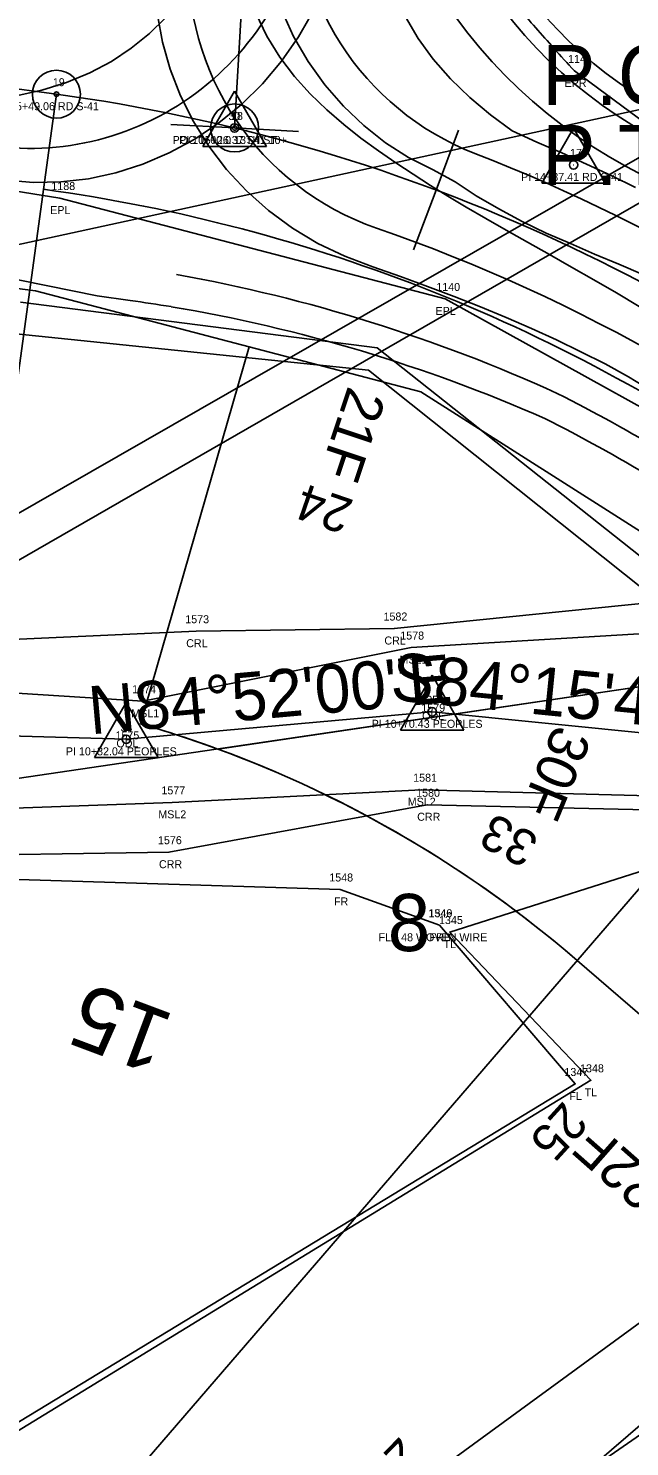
# Model space of a CAD drawing. Extents: x 1812113 to 1819860, y 1177290 to 1181185.
# Drawn here: x 1813637.8 to 1813713, y 1178588.3 to 1178765.6 of the extents above; entities that cross this region are included whole.
import ezdxf

# ---------------------------------------------------------------- set-up
doc = ezdxf.new("R2010")
doc.units = 0
for name, color, linetype in [('RD_EX_DV_Prop', 7, 'Continuous'), ('RD_EX_DV_TX_Prop', 7, 'Continuous'), ('RD_EX_Fence_Other', 7, 'Continuous'), ('RD_EX_Fence_Other_txCode', 7, 'Continuous'), ('RD_EX_H2O', 7, 'Continuous'), ('RD_EX_H2O_txCode', 7, 'Continuous'), ('RD_EX_Misc', 7, 'Continuous'), ('RD_EX_Misc_txCode', 7, 'Continuous'), ('RD_EX_Road', 7, 'Continuous'), ('RD_EX_Road_txCode', 7, 'Continuous'), ('RD_EX_RW', 7, 'Continuous'), ('RD_EX_UT', 7, 'Continuous'), ('RD_EX_VEG', 7, 'Continuous'), ('RD_EX_VEG_txCode', 7, 'Continuous'), ('RD_HC_CL', 7, 'Continuous'), ('RD_HC_Data', 7, 'Continuous'), ('RD_HC_Data_Tic', 7, 'Continuous'), ('RD_HC_TX_Sta50', 7, 'Continuous'), ('RD_HC_TX_StaOther', 7, 'Continuous'), ('RD_HC_txCode', 7, 'Continuous'), ('RD_PD_ALT1_TnTmp', 7, 'Continuous'), ('RD_PD_ALT1_TrvlWay', 7, 'Continuous'), ('RD_PD_CstnLmt', 7, 'Continuous'), ('RD_PD_DR_ErosCtrl', 7, 'Continuous'), ('RD_PD_GR', 7, 'Continuous'), ('RD_PD_PatLn1', 7, 'Continuous'), ('RD_PD_PatLn2', 7, 'Continuous'), ('RD_PD_RW', 7, 'Continuous'), ('RD_Sketch5', 7, 'Continuous'), ('RD_Sketch7', 7, 'Continuous'), ('RD_Sketch8', 7, 'Continuous'), ('RD_SMD_Locator', 7, 'Continuous'), ('ROW_Obtain_T3', 7, 'Continuous')]:
    doc.layers.add(name, color=color, linetype=linetype)

msp = doc.modelspace()

# ---------------------------------------------------------------- linework, layer by layer
at = {"layer": 'RD_EX_DV_Prop'}
msp.add_line((1813739.05, 1178686.93), (1813534.09, 1178656.72), dxfattribs=at)
at = {"layer": 'RD_EX_Fence_Other'}
for points in [[(1813495.44, 1178671.73), (1813524.97, 1178674.61), (1813567.3, 1178667.34), (1813625.77, 1178659.53), (1813676.75, 1178657.94), (1813689.16, 1178653.47)], [(1813689.16, 1178653.47), (1813706.15, 1178633.63), (1813541.42, 1178533.61)]]:
    msp.add_lwpolyline(points, dxfattribs=at)
at = {"layer": 'RD_EX_H2O'}
for points in [[(1813499.62, 1178706.37), (1813533.11, 1178716.31), (1813566.87, 1178706.45), (1813581.02, 1178703.79), (1813602.73, 1178697.66), (1813630.18, 1178688.94), (1813658.74, 1178690.22), (1813683.52, 1178690.56), (1813733.77, 1178695.63), (1813767.86, 1178725.16), (1813778.94, 1178729.95)], [(1813494.93, 1178677.14), (1813538.08, 1178685.02), (1813548.67, 1178684.4), (1813554.06, 1178674.83), (1813572.78, 1178667.8), (1813599.8, 1178663.18), (1813623.26, 1178662.12), (1813655.35, 1178662.6), (1813687.65, 1178668.53), (1813720.68, 1178667.78), (1813740.16, 1178669.89), (1813749.02, 1178672.08), (1813765.42, 1178660.89)]]:
    msp.add_lwpolyline(points, dxfattribs=at)
at = {"layer": 'RD_EX_Misc'}
for points in [[(1813405.71, 1178572.74), (1813779.17, 1178786.7), (1813799.35, 1179222.21)], [(1813408.47, 1178567.92), (1813786.33, 1178785.29), (1813804.76, 1179221.83)], [(1813573.26, 1178698.61), (1813581.18, 1178685.42), (1813588.27, 1178683.03), (1813621.87, 1178683.41), (1813652.09, 1178681.47), (1813685.62, 1178688.18), (1813723.85, 1178690.46), (1813735.91, 1178692.91), (1813768.22, 1178723.13), (1813784.54, 1178734.4), (1813800.79, 1178738.46), (1813839.24, 1178736.87), (1813863.9, 1178734.39), (1813884.49, 1178732.56), (1813903.28, 1178733.23)], [(1813591.15, 1178668.77), (1813628.98, 1178667.84), (1813655.76, 1178668.83), (1813686.95, 1178670.41), (1813726.51, 1178669.36), (1813738.94, 1178670.71), (1813788.68, 1178718.19), (1813806.25, 1178725.66), (1813819.18, 1178726.19), (1813847.08, 1178721.31), (1813860.38, 1178717.65), (1813871.97, 1178724.25), (1813883.92, 1178723.48), (1813902.67, 1178722.42)]]:
    msp.add_lwpolyline(points, dxfattribs=at)
at = {"layer": 'RD_EX_Road'}
msp.add_line((1813739.94, 1178735.23), (1813706.04, 1178760.25), dxfattribs=at)
msp.add_lwpolyline([(1813732.94, 1178707.95), (1813689.88, 1178731.75), (1813641.71, 1178744.36), (1813593.37, 1178752.09), (1813544.49, 1178758.77), (1813495.45, 1178766.29), (1813446.8, 1178774.66), (1813426.54, 1178777.95), (1813403.21, 1178782.55), (1813398.65, 1178783.84), (1813350.68, 1178796.09), (1813343.23, 1178797.92), (1813318.7, 1178804.23), (1813303.26, 1178808.85), (1813256.8, 1178823.17), (1813209.81, 1178838.91), (1813163.27, 1178855.57)], dxfattribs=at)
msp.add_open_spline([(1813706.04, 1178760.25), (1813693.68, 1178773.78), (1813687.15, 1178785.68), (1813683.91, 1178796.53)], degree=2, dxfattribs=at)
at = {"layer": 'RD_EX_RW'}
for p, q in [((1813539.17, 1178745.92), (1813638.67, 1178732.75)), ((1813638.67, 1178732.75), (1813686.84, 1178720.14)), ((1813686.84, 1178720.14), (1813739.05, 1178686.93)), ((1813724.98, 1178611.66), (1813565.45, 1178495.22))]:
    msp.add_line(p, q, dxfattribs=at)
at = {"layer": 'RD_EX_UT'}
msp.add_lwpolyline([(1813817.45, 1178777.9), (1813490.2, 1178706.76), (1813294.33, 1178669.42)], dxfattribs=at)
at = {"layer": 'RD_EX_VEG'}
msp.add_lwpolyline([(1813569.58, 1178500.76), (1813635.35, 1178535.15), (1813737.8, 1178606.06), (1813775.9, 1178641.25), (1813752.75, 1178672.45), (1813690.46, 1178652.62), (1813708.11, 1178634.09), (1813540.71, 1178531.72)], dxfattribs=at)
at = {"layer": 'RD_HC_CL'}
for p, q in [((1813663.56, 1178753.12), (1813680.53, 1179052.64)), ((1813641.28, 1178757.34), (1813538.22, 1178771.42)), ((1813650.02, 1178676.71), (1813688.26, 1178680.15)), ((1813688.26, 1178680.15), (1813722.87, 1178676.67)), ((1813618, 1178677.68), (1813650.02, 1178676.71))]:
    msp.add_line(p, q, dxfattribs=at)
msp.add_arc((1813611.44, 1178539), 220.37, 49.2184, 82.2191, dxfattribs=at)
at = {"layer": 'RD_HC_Data'}
for p, q in [((1813641.28, 1178757.34), (1813620.6, 1178606.01)), ((1813659.59, 1178750.82), (1813663.56, 1178757.7)), ((1813663.56, 1178757.7), (1813667.53, 1178750.82)), ((1813701.98, 1178746.21), (1813705.95, 1178753.09)), ((1813705.95, 1178753.09), (1813709.92, 1178746.21)), ((1813659.59, 1178750.82), (1813667.53, 1178750.82)), ((1813701.98, 1178746.21), (1813709.92, 1178746.21)), ((1813755.38, 1178705.86), (1813645.02, 1178577.93)), ((1813684.29, 1178677.85), (1813688.26, 1178684.73)), ((1813688.26, 1178684.73), (1813692.23, 1178677.85)), ((1813646.05, 1178674.42), (1813650.02, 1178681.3)), ((1813650.02, 1178681.3), (1813653.99, 1178674.42)), ((1813684.29, 1178677.85), (1813692.23, 1178677.85)), ((1813646.05, 1178674.42), (1813653.99, 1178674.42))]:
    msp.add_line(p, q, dxfattribs=at)
for centre, radius in [((1813641.28, 1178757.34), 3), ((1813641.28, 1178757.34), 0.282), ((1813663.56, 1178753.12), 3), ((1813663.56, 1178753.12), 0.529), ((1813663.56, 1178753.12), 0.282), ((1813705.95, 1178748.5), 0.529), ((1813688.26, 1178680.15), 0.529), ((1813650.02, 1178676.71), 0.529)]:
    msp.add_circle(centre, radius, dxfattribs=at)
at = {"layer": 'RD_HC_Data_Tic'}
for p, q in [((1813663.56, 1178753.12), (1813655.57, 1178753.57)), ((1813663.56, 1178753.12), (1813671.54, 1178752.66)), ((1813688.75, 1178745.36), (1813691.55, 1178752.85)), ((1813688.75, 1178745.36), (1813685.94, 1178737.87))]:
    msp.add_line(p, q, dxfattribs=at)
at = {"layer": 'RD_PD_ALT1_TrvlWay'}
for centre, radius, start, end in [((1813743.64, 1178805.37), 65, 176.7565, 243.6045), ((1813611.44, 1178539), 208.37, 54.383, 82.2191)]:
    msp.add_arc(centre, radius, start, end, dxfattribs=at)
at = {"layer": 'RD_PD_CstnLmt'}
for p, q in [((1813636.78, 1178731.34), (1813681.37, 1178725.65)), ((1813681.37, 1178725.65), (1813714.27, 1178699.59))]:
    msp.add_line(p, q, dxfattribs=at)
msp.add_arc((1813611.44, 1178539), 255.97, 56.8168, 69.1681, dxfattribs=at)
at = {"layer": 'RD_PD_DR_ErosCtrl'}
for p, q in [((1813680.31, 1178722.84), (1813636.23, 1178727.38)), ((1813714.98, 1178695.21), (1813680.31, 1178722.84)), ((1813732.88, 1178606.97), (1813693.96, 1178573.58))]:
    msp.add_line(p, q, dxfattribs=at)
msp.add_arc((1813611.44, 1178539), 258.97, 56.8421, 70.5446, dxfattribs=at)
at = {"layer": 'RD_PD_GR'}
for centre, radius, start, end in [((1813743.64, 1178803.52), 58.53, 176.7565, 245.2829), ((1813620.41, 1178536.16), 201.87, 65.5658, 79.7574), ((1813613.06, 1178539.68), 201.87, 54.383, 63.2527)]:
    msp.add_arc(centre, radius, start, end, dxfattribs=at)
at = {"layer": 'RD_PD_PatLn1'}
for p, q in [((1813646.37, 1178732.12), (1813583.13, 1178745.1)), ((1813650.52, 1178731.55), (1813646.37, 1178732.12))]:
    msp.add_line(p, q, dxfattribs=at)
for centre, radius, start, end in [((1813743.64, 1178803.52), 55.03, 176.7565, 245.4118), ((1813623.98, 1178537.34), 196.02, 80.7081, 82.2191), ((1813622.89, 1178536.19), 197.33, 66.2576, 80.4492), ((1813613.06, 1178539.68), 198.37, 54.383, 63.2527)]:
    msp.add_arc(centre, radius, start, end, dxfattribs=at)
at = {"layer": 'RD_PD_PatLn2'}
for p, q in [((1813665.4, 1178725.75), (1813651.79, 1178678.65)), ((1813686.84, 1178720.14), (1813665.4, 1178725.75)), ((1813739.05, 1178686.93), (1813686.84, 1178720.14)), ((1813661.45, 1178675.49), (1813739.05, 1178686.93))]:
    msp.add_line(p, q, dxfattribs=at)
msp.add_arc((1813611.44, 1178539), 145.37, 69.8791, 73.8831, dxfattribs=at)
at = {"layer": 'RD_PD_RW'}
for p, q in [((1813665.4, 1178725.75), (1813651.79, 1178678.65)), ((1813739, 1178620.94), (1813706.39, 1178649.07))]:
    msp.add_line(p, q, dxfattribs=at)
msp.add_arc((1813611.44, 1178539), 145.37, 49.2184, 73.8831, dxfattribs=at)
at = {"layer": 'RD_Sketch5'}
for points in [[(1813635.05, 1178746.58), (1813638.4, 1178746.3), (1813641.82, 1178746.37), (1813645.27, 1178746.77), (1813648.71, 1178747.52), (1813652.09, 1178748.6), (1813655.39, 1178750.01), (1813658.57, 1178751.73), (1813661.59, 1178753.75), (1813664.42, 1178756.07), (1813667.04, 1178758.64), (1813669.42, 1178761.47), (1813671.53, 1178764.51), (1813672.83, 1178766.76)], [(1813636.23, 1178757.12), (1813639.45, 1178757.84), (1813642.53, 1178758.8), (1813645.44, 1178760.01), (1813648.15, 1178761.44), (1813650.64, 1178763.08), (1813652.91, 1178764.91), (1813654.93, 1178766.9)]]:
    msp.add_lwpolyline(points, dxfattribs=at)
msp.add_arc((1813637.85, 1178785.56), 35, 262.2191, 356.7565, dxfattribs=at)
at = {"layer": 'RD_Sketch7'}
for points in [[(1813714.62, 1178734.82), (1813711.6, 1178736.09), (1813708.56, 1178737.34), (1813705.54, 1178738.66), (1813702.5, 1178739.99), (1813699.5, 1178741.42), (1813696.61, 1178743), (1813693.78, 1178744.63), (1813691.15, 1178746.39), (1813688.31, 1178747.93), (1813685.32, 1178749.45), (1813682.43, 1178751.27), (1813679.7, 1178753.41), (1813677.16, 1178755.83), (1813674.83, 1178758.51), (1813672.75, 1178761.44), (1813670.94, 1178764.57), (1813669.42, 1178767.89)], [(1813713.69, 1178745.68), (1813710.63, 1178747.16), (1813707.56, 1178748.6), (1813704.46, 1178750), (1813701.34, 1178751.34), (1813698.28, 1178752.76), (1813695.55, 1178754.75), (1813692.96, 1178756.91), (1813690.56, 1178759.25), (1813688.4, 1178761.72), (1813686.52, 1178764.32), (1813684.92, 1178767)]]:
    msp.add_lwpolyline(points, dxfattribs=at)
for centre, radius, start, end in [((1813706.29, 1178782.55), 35, 176.7565, 248.722), ((1813611.44, 1178539), 226.37, 49.2184, 68.722)]:
    msp.add_arc(centre, radius, start, end, dxfattribs=at)
at = {"layer": 'RD_Sketch8'}
for points in [[(1813653.92, 1178767.27), (1813654.53, 1178763.84), (1813655.49, 1178760.45), (1813656.78, 1178757.13), (1813658.4, 1178753.91), (1813660.33, 1178750.84), (1813662.55, 1178747.94), (1813665.05, 1178745.25), (1813667.8, 1178742.8), (1813670.79, 1178740.6), (1813673.98, 1178738.69), (1813677.34, 1178737.08), (1813680.84, 1178735.77), (1813684.3, 1178734.55), (1813687.7, 1178733.32), (1813691.03, 1178732.05), (1813694.3, 1178730.76), (1813697.52, 1178729.42), (1813700.68, 1178728.04), (1813703.79, 1178726.62), (1813706.86, 1178725.16), (1813709.88, 1178723.65), (1813712.82, 1178722.03), (1813715.67, 1178720.26)], [(1813666.21, 1178767.45), (1813667.61, 1178764.6), (1813669.23, 1178761.95), (1813671.03, 1178759.54), (1813673, 1178757.37), (1813675.08, 1178755.38), (1813677.2, 1178753.55), (1813679.36, 1178751.86), (1813681.54, 1178750.27), (1813683.72, 1178748.76), (1813685.89, 1178747.33), (1813688.06, 1178745.95), (1813690.22, 1178744.61), (1813692.51, 1178743.23), (1813694.96, 1178741.79), (1813697.53, 1178740.34), (1813700.19, 1178738.84), (1813702.92, 1178737.3), (1813705.68, 1178735.73), (1813708.49, 1178734.13), (1813711.31, 1178732.5), (1813714.13, 1178730.82)]]:
    msp.add_lwpolyline(points, dxfattribs=at)
for centre, radius, start, end in [((1813692.77, 1178773.67), 35, 176.7565, 250.8867), ((1813611.44, 1178539), 213.37, 49.2184, 70.8867)]:
    msp.add_arc(centre, radius, start, end, dxfattribs=at)
at = {"layer": 'RD_SMD_Locator'}
for centre in [(1813706.04, 1178760.25), (1813641.28, 1178757.34), (1813663.56, 1178753.12), (1813663.56, 1178753.12), (1813705.95, 1178748.5), (1813641.71, 1178744.36), (1813689.88, 1178731.75), (1813658.74, 1178690.22), (1813683.52, 1178690.56), (1813685.62, 1178688.18), (1813652.09, 1178681.47), (1813688.26, 1178680.15), (1813688.26, 1178680.15), (1813650.02, 1178676.71), (1813650.02, 1178676.71), (1813686.95, 1178670.41), (1813655.76, 1178668.83), (1813687.65, 1178668.53), (1813655.35, 1178662.6), (1813676.75, 1178657.94), (1813689.16, 1178653.47), (1813689.16, 1178653.47), (1813690.46, 1178652.62), (1813706.15, 1178633.63), (1813708.11, 1178634.09)]:
    msp.add_circle(centre, 0.001, dxfattribs=at)
at = {"layer": 'ROW_Obtain_T3'}
for p, q in [((1813739.05, 1178686.93), (1813661.45, 1178675.49)), ((1813706.39, 1178649.07), (1813739, 1178620.94))]:
    msp.add_line(p, q, dxfattribs=at)
msp.add_arc((1813611.44, 1178539), 145.37, 49.2184, 69.8791, dxfattribs=at)

# ---------------------------------------------------------------- texts
at = {"layer": 'RD_EX_DV_TX_Prop'}
msp.add_text('8', height=7.14, dxfattribs=at).set_placement((1813682.71, 1178650.24))
at = {"layer": 'RD_EX_Fence_Other_txCode'}
for s, p in [('1548', (1813675.4, 1178658.94)), ('FR', (1813675.99, 1178655.94)), ('1346', (1813687.79, 1178654.47)), ('1549', (1813687.82, 1178654.47)), ('FLA 48 WOVEN WIRE', (1813681.56, 1178651.47)), ('FRB', (1813687.93, 1178651.47)), ('1347', (1813704.8, 1178634.63)), ('FL', (1813705.42, 1178631.63))]:
    msp.add_text(s, height=1, dxfattribs=at).set_placement(p)
at = {"layer": 'RD_EX_H2O_txCode'}
for s, p in [('1573', (1813657.39, 1178691.22)), ('1582', (1813682.18, 1178691.56)), ('CRL', (1813682.29, 1178688.56)), ('CRL', (1813657.51, 1178688.22)), ('1579', (1813686.91, 1178680.15)), ('ODL', (1813687.01, 1178679.15)), ('1575', (1813648.67, 1178676.71)), ('ODL', (1813648.78, 1178675.71)), ('1580', (1813686.26, 1178669.53)), ('CRR', (1813686.39, 1178666.53)), ('1576', (1813653.98, 1178663.6)), ('CRR', (1813654.1, 1178660.6))]:
    msp.add_text(s, height=1, dxfattribs=at).set_placement(p)
at = {"layer": 'RD_EX_Misc_txCode'}
for s, p in [('1578', (1813684.28, 1178689.18)), ('MSL1', (1813684.17, 1178686.18)), ('1574', (1813650.75, 1178682.47)), ('MSL1', (1813650.64, 1178679.47)), ('1581', (1813685.89, 1178671.41)), ('1577', (1813654.41, 1178669.83)), ('MSL2', (1813685.21, 1178668.41)), ('MSL2', (1813654.02, 1178666.83))]:
    msp.add_text(s, height=1, dxfattribs=at).set_placement(p)
at = {"layer": 'RD_EX_Road_txCode'}
for s, p in [('1141', (1813705.26, 1178761.25)), ('EPR', (1813704.81, 1178758.25)), ('1188', (1813640.65, 1178745.36)), ('EPL', (1813640.5, 1178742.36)), ('1140', (1813688.78, 1178732.75)), ('EPL', (1813688.68, 1178729.75))]:
    msp.add_text(s, height=1, dxfattribs=at).set_placement(p)
at = {"layer": 'RD_EX_VEG_txCode'}
for s, p in [('1345', (1813689.12, 1178653.62)), ('TL', (1813689.69, 1178650.62)), ('1348', (1813706.76, 1178635.09)), ('TL', (1813707.33, 1178632.09))]:
    msp.add_text(s, height=1, dxfattribs=at).set_placement(p)
at = {"layer": 'RD_HC_TX_Sta50'}
msp.add_text('15', height=8, rotation=159.4631, dxfattribs=at).set_placement((1813656.25, 1178642.2))
at = {"layer": 'RD_HC_TX_StaOther'}
for s, p in [('P.C. - LG% = ', (1813702, 1178756)), ('P.T. - LG% = ', (1813702, 1178746))]:
    msp.add_text(s, height=7.5, dxfattribs=at).set_placement(p)
at = {"layer": 'RD_HC_txCode'}
for s, p in [('19', (1813640.83, 1178758.34)), ('PT 15+49.06 RD S-41', (1813633.4, 1178755.34)), ('30', (1813662.78, 1178754.12)), ('18', (1813663.11, 1178754.12)), ('POC 15+26.37 S41 10+', (1813655.81, 1178751.12)), ('PI 10+00.0 13TH ST', (1813656.62, 1178751.12)), ('17', (1813705.5, 1178749.5)), ('PI 14+87.41 RD S-41', (1813699.38, 1178746.5)), ('35', (1813687.53, 1178681.15)), ('34', (1813649.29, 1178677.71)), ('PI 10+70.43 PEOPLES', (1813680.7, 1178678.15)), ('PI 10+32.04 PEOPLES', (1813642.46, 1178674.71))]:
    msp.add_text(s, height=1, dxfattribs=at).set_placement(p)
at = {"layer": 'RD_PD_ALT1_TnTmp'}
for s, rotation, p in [('S84%%d15\'46"E', 354.2627, (1813682.94, 1178681.68)), ('N84%%d52\'00"E', 5.1334, (1813645.57, 1178677.32))]:
    msp.add_text(s, height=6, rotation=rotation, dxfattribs=at).set_placement(p)
at = {"layer": 'RD_PD_CstnLmt'}
for s, rotation, p in [('21F', 251.5416, (1813677.79, 1178721.01)), ('30F', 247.5268, (1813703.64, 1178678.73)), ('22F', 138.6285, (1813717.52, 1178621.19))]:
    msp.add_text(s, height=5, rotation=rotation, dxfattribs=at).set_placement(p)
at = {"layer": 'RD_PD_DR_ErosCtrl'}
for s, rotation, p in [('24', 160.9842, (1813678.63, 1178706.54)), ('33', 152.9324, (1813701.84, 1178664.53)), ('25', 227.7077, (1813704.72, 1178631.63)), ('21', 225.4663, (1813684.29, 1178589.7))]:
    msp.add_text(s, height=4.5, rotation=rotation, dxfattribs=at).set_placement(p)

doc.saveas('drawing.dxf')
